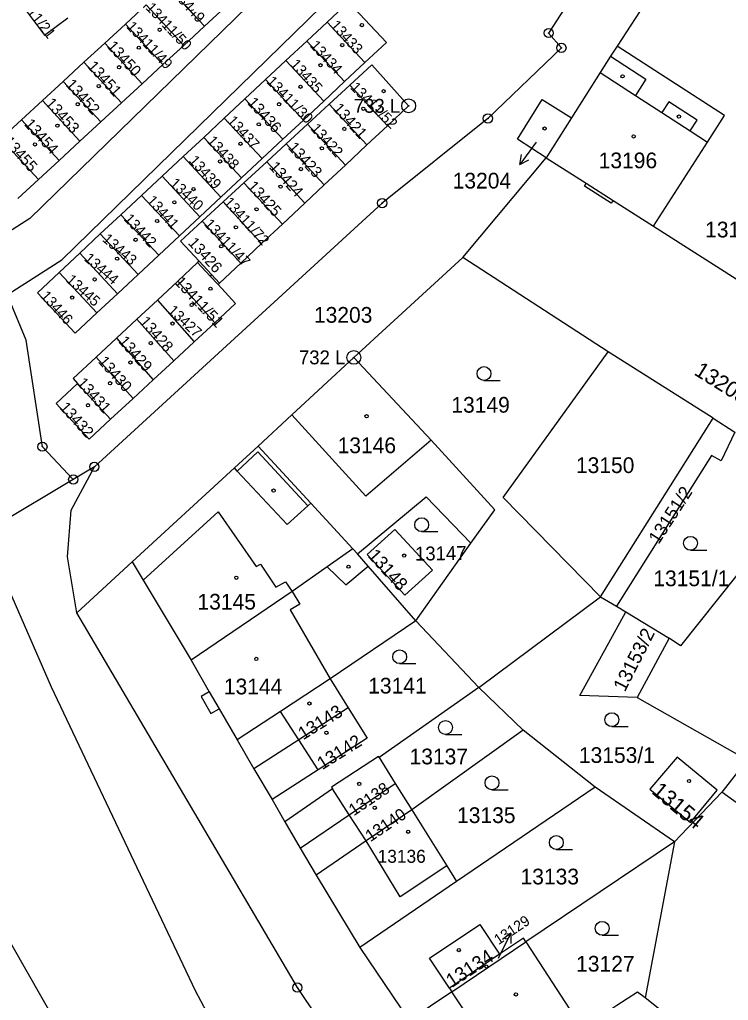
# Model space of a CAD drawing. Extents: x -821458 to -820266, y -1071458 to -1069826.
# Drawn here: x -820643.1 to -820566.5, y -1071211.7 to -1071105.6 of the extents above; entities that cross this region are included whole.
import ezdxf

# ---------------------------------------------------------------- set-up
doc = ezdxf.new("R2010")
doc.units = 0
for name, color, linetype in [('Vrstva 1', 7, 'Continuous'), ('Vrstva 13', 7, 'Continuous'), ('Vrstva 2', 7, 'Continuous'), ('Vrstva 3', 7, 'Continuous'), ('Vrstva 4', 7, 'Continuous'), ('Vrstva 5', 7, 'Continuous'), ('Vrstva 6', 7, 'Continuous'), ('Vrstva 7', 7, 'Continuous'), ('Vrstva 8', 7, 'Continuous')]:
    doc.layers.add(name, color=color, linetype=linetype)

msp = doc.modelspace()

# ---------------------------------------------------------------- linework, layer by layer
at = {"layer": 'Vrstva 1'}
for p, q in [((-820571.9, -1071098.21), (-820578.53, -1071108.44)), ((-820623.14, -1071106.28), (-820627.21, -1071101.9)), ((-820629.45, -1071103.96), (-820631.7, -1071106.04)), ((-820625.38, -1071108.35), (-820629.45, -1071103.96)), ((-820623.14, -1071106.28), (-820620.9, -1071104.22)), ((-820609.89, -1071105.82), (-820612.09, -1071107.88)), ((-820609.89, -1071105.82), (-820605.79, -1071110.2)), ((-820631.7, -1071106.04), (-820633.93, -1071108.1)), ((-820631.7, -1071106.04), (-820627.63, -1071110.43)), ((-820625.38, -1071108.35), (-820623.14, -1071106.28)), ((-820612.09, -1071107.88), (-820614.34, -1071109.99)), ((-820612.09, -1071107.88), (-820608, -1071112.27)), ((-820633.93, -1071108.1), (-820636.17, -1071110.17)), ((-820633.93, -1071108.1), (-820629.87, -1071112.49)), ((-820627.63, -1071110.43), (-820625.38, -1071108.35)), ((-820614.34, -1071109.99), (-820616.55, -1071112.05)), ((-820610.25, -1071114.37), (-820614.34, -1071109.99)), ((-820636.17, -1071110.17), (-820638.42, -1071112.24)), ((-820636.17, -1071110.17), (-820632.11, -1071114.55)), ((-820629.87, -1071112.49), (-820627.63, -1071110.43)), ((-820608, -1071112.27), (-820605.79, -1071110.2)), ((-820616.55, -1071112.05), (-820618.78, -1071114.13)), ((-820616.55, -1071112.05), (-820612.45, -1071116.43)), ((-820638.42, -1071112.24), (-820640.67, -1071114.32)), ((-820638.42, -1071112.24), (-820634.35, -1071116.62)), ((-820632.11, -1071114.55), (-820629.87, -1071112.49)), ((-820610.25, -1071114.37), (-820608, -1071112.27)), ((-820607.43, -1071112.65), (-820609.66, -1071114.71)), ((-820607.43, -1071112.65), (-820603.37, -1071117.05)), ((-820618.78, -1071114.13), (-820621, -1071116.22)), ((-820618.78, -1071114.13), (-820614.68, -1071118.51)), ((-820640.67, -1071114.32), (-820642.94, -1071116.4)), ((-820640.67, -1071114.32), (-820636.61, -1071118.7)), ((-820634.35, -1071116.62), (-820632.11, -1071114.55)), ((-820612.45, -1071116.43), (-820610.25, -1071114.37)), ((-820609.66, -1071114.71), (-820611.99, -1071116.86)), ((-820609.66, -1071114.71), (-820605.58, -1071119.12)), ((-820642.94, -1071116.4), (-820645.16, -1071118.45)), ((-820642.94, -1071116.4), (-820638.87, -1071120.79)), ((-820621, -1071116.22), (-820623.23, -1071118.3)), ((-820621, -1071116.22), (-820616.91, -1071120.6)), ((-820614.68, -1071118.51), (-820612.45, -1071116.43)), ((-820583.46, -1071116.19), (-820586.18, -1071120.5)), ((-820636.61, -1071118.7), (-820634.35, -1071116.62)), ((-820611.99, -1071116.86), (-820614.3, -1071118.99)), ((-820611.99, -1071116.86), (-820607.9, -1071121.29)), ((-820605.58, -1071119.12), (-820603.37, -1071117.05)), ((-820645.16, -1071118.45), (-820641.09, -1071122.84)), ((-820623.23, -1071118.3), (-820625.46, -1071120.38)), ((-820623.23, -1071118.3), (-820619.14, -1071122.68)), ((-820616.91, -1071120.6), (-820614.68, -1071118.51)), ((-820638.87, -1071120.79), (-820636.61, -1071118.7)), ((-820614.3, -1071118.99), (-820616.41, -1071120.93)), ((-820614.3, -1071118.99), (-820610.19, -1071123.45)), ((-820607.9, -1071121.29), (-820605.58, -1071119.12)), ((-820625.46, -1071120.38), (-820627.72, -1071122.5)), ((-820625.46, -1071120.38), (-820621.36, -1071124.76)), ((-820619.14, -1071122.68), (-820616.91, -1071120.6)), ((-820595.21, -1071131.28), (-820586.18, -1071120.5)), ((-820641.09, -1071122.84), (-820638.87, -1071120.79)), ((-820616.41, -1071120.93), (-820618.87, -1071123.2)), ((-820616.41, -1071120.93), (-820612.28, -1071125.4)), ((-820610.19, -1071123.45), (-820607.9, -1071121.29)), ((-820627.72, -1071122.5), (-820629.95, -1071124.58)), ((-820627.72, -1071122.5), (-820623.63, -1071126.88)), ((-820621.36, -1071124.76), (-820619.14, -1071122.68)), ((-820643.33, -1071124.91), (-820641.09, -1071122.84)), ((-820618.87, -1071123.2), (-820621.12, -1071125.28)), ((-820618.87, -1071123.2), (-820614.72, -1071127.69)), ((-820612.28, -1071125.4), (-820610.19, -1071123.45)), ((-820629.95, -1071124.58), (-820632.18, -1071126.67)), ((-820629.95, -1071124.58), (-820625.86, -1071128.96)), ((-820623.63, -1071126.88), (-820621.36, -1071124.76)), ((-820621.12, -1071125.28), (-820623.38, -1071127.37)), ((-820616.96, -1071129.79), (-820621.12, -1071125.28)), ((-820614.72, -1071127.69), (-820612.28, -1071125.4)), ((-820632.18, -1071126.67), (-820634.41, -1071128.75)), ((-820632.18, -1071126.67), (-820628.08, -1071131.05)), ((-820625.86, -1071128.96), (-820623.63, -1071126.88)), ((-820623.38, -1071127.37), (-820619.2, -1071131.89)), ((-820616.96, -1071129.79), (-820614.72, -1071127.69)), ((-820574.58, -1071127.9), (-820563.75, -1071134.82)), ((-820634.41, -1071128.75), (-820636.63, -1071130.83)), ((-820634.41, -1071128.75), (-820630.31, -1071133.13)), ((-820628.08, -1071131.05), (-820625.86, -1071128.96)), ((-820619.2, -1071131.89), (-820616.96, -1071129.79)), ((-820636.63, -1071130.83), (-820638.86, -1071132.91)), ((-820636.63, -1071130.83), (-820632.54, -1071135.21)), ((-820630.31, -1071133.13), (-820628.08, -1071131.05)), ((-820595.21, -1071131.28), (-820607, -1071142.1)), ((-820579.48, -1071141.51), (-820595.21, -1071131.28)), ((-820638.86, -1071132.91), (-820634.77, -1071137.29)), ((-820632.54, -1071135.21), (-820630.31, -1071133.13)), ((-820626.04, -1071133.86), (-820628.24, -1071135.91)), ((-820622.04, -1071138.36), (-820626.04, -1071133.86)), ((-820634.77, -1071137.29), (-820632.54, -1071135.21)), ((-820628.24, -1071135.91), (-820630.45, -1071137.97)), ((-820628.24, -1071135.91), (-820624.25, -1071140.4)), ((-820630.45, -1071137.97), (-820632.66, -1071140.03)), ((-820630.45, -1071137.97), (-820626.46, -1071142.46)), ((-820624.25, -1071140.4), (-820622.04, -1071138.36)), ((-820632.66, -1071140.03), (-820634.84, -1071142.06)), ((-820632.66, -1071140.03), (-820628.68, -1071144.51)), ((-820626.46, -1071142.46), (-820624.25, -1071140.4)), ((-820568.13, -1071148.68), (-820579.48, -1071141.51)), ((-820634.84, -1071142.06), (-820630.87, -1071146.53)), ((-820628.68, -1071144.51), (-820626.46, -1071142.46)), ((-820636.86, -1071144.91), (-820633.29, -1071148.77)), ((-820630.87, -1071146.53), (-820628.68, -1071144.51)), ((-820633.29, -1071148.77), (-820630.87, -1071146.53)), ((-820580.31, -1071167.99), (-820568.13, -1071148.68)), ((-820568.13, -1071148.68), (-820565.8, -1071150.18)), ((-820635.05, -1071153.94), (-820637.33, -1071155.3)), ((-820637.33, -1071155.3), (-820662, -1071170.07)), ((-820606.61, -1071163.36), (-820607.09, -1071162.81)), ((-820600.3, -1071170.6), (-820594.33, -1071162.21)), ((-820636.96, -1071169.72), (-820630.96, -1071164.21)), ((-820593.49, -1071177.8), (-820580.31, -1071167.99)), ((-820580.31, -1071167.99), (-820578.6, -1071169.02)), ((-820578.6, -1071169.02), (-820577.58, -1071169.64)), ((-820577.58, -1071169.64), (-820572.9, -1071172.46)), ((-820600.3, -1071170.6), (-820609.55, -1071176.86)), ((-820593.49, -1071177.8), (-820600.3, -1071170.6)), ((-820572.9, -1071172.46), (-820576.35, -1071178.9)), ((-820609.55, -1071176.86), (-820607.6, -1071180)), ((-820593.49, -1071177.8), (-820604.26, -1071185.37)), ((-820588.7, -1071182.42), (-820593.49, -1071177.8)), ((-820576.35, -1071178.9), (-820564.47, -1071185.62)), ((-820588.7, -1071182.42), (-820600.74, -1071191.03)), ((-820580.89, -1071188.58), (-820588.7, -1071182.42)), ((-820619.61, -1071183.48), (-820617.79, -1071186.59)), ((-820604.26, -1071185.37), (-820602.51, -1071188.18)), ((-820564.47, -1071185.62), (-820567.22, -1071189.13)), ((-820617.79, -1071186.59), (-820615.84, -1071189.94)), ((-820602.51, -1071188.18), (-820600.74, -1071191.03)), ((-820580.89, -1071188.58), (-820595.88, -1071198.8)), ((-820572.31, -1071194.51), (-820580.89, -1071188.58)), ((-820567.22, -1071189.13), (-820572.31, -1071194.51)), ((-820615.84, -1071189.94), (-820614.45, -1071192.34)), ((-820614.45, -1071192.34), (-820612.78, -1071195.19)), ((-820572.31, -1071194.51), (-820588.39, -1071205.33)), ((-820572.31, -1071194.51), (-820575.48, -1071211.38)), ((-820612.78, -1071195.19), (-820611.07, -1071198.11)), ((-820611.07, -1071198.11), (-820606.35, -1071205.94)), ((-820595.88, -1071198.8), (-820606.35, -1071205.94)), ((-820596.4, -1071210.72), (-820588.39, -1071205.33)), ((-820588.39, -1071205.33), (-820582.26, -1071214.75)), ((-820606.35, -1071205.94), (-820601.01, -1071213.82)), ((-820591.23, -1071206.67), (-820596.65, -1071210.34)), ((-820596.4, -1071210.72), (-820601.01, -1071213.82)), ((-820596.65, -1071210.34), (-820596.4, -1071210.72)), ((-820590.11, -1071220.12), (-820596.4, -1071210.72)), ((-820565.25, -1071219.52), (-820575.48, -1071211.38))]:
    msp.add_line(p, q, dxfattribs=at)
for points in [[(-820637.33, -1071155.3), (-820640.67, -1071151.76), (-820642.44, -1071140.23), (-820649.73, -1071122.67), (-820650.36, -1071093.83)], [(-820571.9, -1071098.21), (-820578.09, -1071094.87), (-820585.93, -1071107.01), (-820584.55, -1071108.62), (-820592.5, -1071116.26), (-820603.93, -1071125.41), (-820635.05, -1071153.94)], [(-820641.91, -1071100.01), (-820644.43, -1071101.87), (-820640.43, -1071107.25), (-820637.92, -1071105.38)], [(-820605.79, -1071110.2), (-820603.47, -1071108.04), (-820607.58, -1071103.67), (-820609.89, -1071105.82)], [(-820578.53, -1071108.44), (-820579.23, -1071109.52), (-820580.37, -1071111.29), (-820583.46, -1071116.19)], [(-820574.58, -1071127.9), (-820568.75, -1071118.8), (-820566.92, -1071115.95), (-820578.53, -1071108.44)], [(-820603.37, -1071117.05), (-820601.07, -1071114.89), (-820605.04, -1071110.45), (-820607.43, -1071112.65)], [(-820586.18, -1071120.5), (-820589.29, -1071118.51), (-820586.63, -1071114.19), (-820583.46, -1071116.19)], [(-820586.18, -1071120.5), (-820581.86, -1071123.26), (-820578.96, -1071125.11), (-820574.58, -1071127.9)], [(-820623.38, -1071127.37), (-820625.74, -1071129.54), (-820623.73, -1071131.7)], [(-820623.73, -1071131.7), (-820623.89, -1071131.85), (-820626.04, -1071133.86)], [(-820623.73, -1071131.7), (-820622.37, -1071133.15), (-820622.53, -1071133.31), (-820621.68, -1071134.22)], [(-820621.68, -1071134.22), (-820621.51, -1071134.06), (-820619.2, -1071131.89)], [(-820638.86, -1071132.91), (-820641.2, -1071135.1), (-820637.11, -1071139.48), (-820634.77, -1071137.29)], [(-820622.04, -1071138.36), (-820619.78, -1071136.28), (-820621.68, -1071134.22)], [(-820580.31, -1071167.99), (-820590.84, -1071157.27), (-820579.48, -1071141.51)], [(-820634.84, -1071142.06), (-820637.34, -1071144.39), (-820636.86, -1071144.91)], [(-820607, -1071142.1), (-820613.71, -1071148.32), (-820617.33, -1071151.69)], [(-820594.33, -1071162.21), (-820591.74, -1071158.58), (-820598.65, -1071151.04), (-820607, -1071142.1)], [(-820636.86, -1071144.91), (-820639.19, -1071147.07), (-820635.62, -1071150.93), (-820633.29, -1071148.77)], [(-820565.8, -1071150.18), (-820567.29, -1071153.29), (-820568.31, -1071152.7), (-820578.6, -1071169.02)], [(-820617.33, -1071151.69), (-820619.91, -1071154.06), (-820630.96, -1071164.21)], [(-820607.09, -1071162.81), (-820611.64, -1071157.87), (-820617.33, -1071151.69)], [(-820636.96, -1071169.72), (-820637.97, -1071163.66), (-820637.57, -1071158.64), (-820635.05, -1071153.94)], [(-820557.49, -1071155.53), (-820571.69, -1071173.31), (-820572.9, -1071172.46)], [(-820606.61, -1071163.36), (-820599.18, -1071157.18), (-820594.33, -1071162.21)], [(-820602.56, -1071160.73), (-820598.48, -1071165.13), (-820601.47, -1071167.82), (-820605.56, -1071163.42), (-820602.56, -1071160.73)], [(-820607.09, -1071162.81), (-820609.89, -1071164.76), (-820613.66, -1071167.42), (-820624.6, -1071174.87)], [(-820600.3, -1071170.6), (-820605.45, -1071164.7), (-820606.61, -1071163.36)], [(-820630.96, -1071164.21), (-820629.77, -1071166.21), (-820624.6, -1071174.87)], [(-820564.58, -1071281.57), (-820567.96, -1071277.63), (-820613.1, -1071210.27), (-820636.96, -1071169.72)], [(-820576.35, -1071178.9), (-820582.57, -1071178.68), (-820577.85, -1071170.1), (-820577.58, -1071169.64)], [(-820624.6, -1071174.87), (-820622.62, -1071178.29), (-820621.57, -1071180.1), (-820619.61, -1071183.48)], [(-820609.55, -1071176.86), (-820614.93, -1071180.4), (-820619.61, -1071183.48)], [(-820607.6, -1071180), (-820612.95, -1071183.46), (-820617.79, -1071186.59)], [(-820607.6, -1071180), (-820605.56, -1071183.29), (-820610.85, -1071186.71), (-820615.84, -1071189.94)], [(-820604.26, -1071185.37), (-820604.33, -1071185.26), (-820609.41, -1071188.59), (-820609.3, -1071188.77), (-820614.45, -1071192.34)], [(-820574.98, -1071188.8), (-820570.6, -1071192.42), (-820567.7, -1071188.92), (-820572.02, -1071185.34), (-820574.98, -1071188.8)], [(-820612.78, -1071195.19), (-820607.49, -1071191.58), (-820602.51, -1071188.18)], [(-820556.62, -1071191.69), (-820558.93, -1071195.12), (-820567.22, -1071189.13)], [(-820600.74, -1071191.03), (-820605.67, -1071194.4), (-820611.07, -1071198.11)], [(-820600.74, -1071191.03), (-820596.94, -1071197.11), (-820595.88, -1071198.8)], [(-820637.88, -1071216.32), (-820639.21, -1071214.01), (-820645.44, -1071203.12)], [(-820596.65, -1071210.34), (-820598.82, -1071207.1), (-820593.37, -1071203.46), (-820591.23, -1071206.67)], [(-820588.39, -1071205.33), (-820588.65, -1071204.92), (-820591.23, -1071206.67)], [(-820575.48, -1071211.38), (-820576.31, -1071210.76), (-820578.57, -1071212.22), (-820579.84, -1071213.09), (-820582.26, -1071214.75)]]:
    msp.add_lwpolyline(points, dxfattribs=at)
at = {"layer": 'Vrstva 13'}
msp.add_lwpolyline([(-820675.1, -1071148.28), (-820672.81, -1071153.44), (-820638.57, -1071131.55), (-820610.44, -1071104.1), (-820600.08, -1071094.97), (-820582.77, -1071081.03), (-820585.78, -1071076.26), (-820603.68, -1071090.69), (-820614.26, -1071100), (-820642.01, -1071127.07)], close=True, dxfattribs=at)
at = {"layer": 'Vrstva 3'}
for p, q in [((-820592.92, -1071144.6), (-820591.17, -1071144.6)), ((-820599.66, -1071160.95), (-820597.91, -1071160.95)), ((-820570.59, -1071162.96), (-820568.84, -1071162.96)), ((-820602.04, -1071175.23), (-820600.29, -1071175.23)), ((-820579.09, -1071182.04), (-820577.34, -1071182.04)), ((-820597.08, -1071182.89), (-820595.33, -1071182.89)), ((-820592.06, -1071188.87), (-820590.31, -1071188.87)), ((-820585.1, -1071195.32), (-820583.35, -1071195.32)), ((-820580.14, -1071204.61), (-820578.39, -1071204.61))]:
    msp.add_line(p, q, dxfattribs=at)
for centre in [(-820592.92, -1071143.85), (-820599.66, -1071160.2), (-820570.59, -1071162.21), (-820602.04, -1071174.48), (-820579.09, -1071181.29), (-820597.08, -1071182.14), (-820592.06, -1071188.12), (-820585.1, -1071194.57), (-820580.14, -1071203.86)]:
    msp.add_circle(centre, 0.75, dxfattribs=at)
at = {"layer": 'Vrstva 4'}
for p, q in [((-820579.23, -1071109.52), (-820575.41, -1071111.99)), ((-820580.37, -1071111.29), (-820576.55, -1071113.76)), ((-820575.41, -1071111.99), (-820576.55, -1071113.76)), ((-820576.55, -1071113.76), (-820573.7, -1071115.6)), ((-820572.95, -1071114.45), (-820573.7, -1071115.6)), ((-820569.87, -1071116.44), (-820572.95, -1071114.45)), ((-820573.7, -1071115.6), (-820570.61, -1071117.6)), ((-820570.61, -1071117.6), (-820569.87, -1071116.44)), ((-820570.61, -1071117.6), (-820568.75, -1071118.8)), ((-820582.05, -1071123.56), (-820581.86, -1071123.26)), ((-820579.16, -1071125.41), (-820582.05, -1071123.56)), ((-820578.96, -1071125.11), (-820579.16, -1071125.41)), ((-820623.89, -1071131.85), (-820622.53, -1071133.31)), ((-820622.37, -1071133.15), (-820621.51, -1071134.06)), ((-820605.68, -1071157.1), (-820613.71, -1071148.32)), ((-820598.65, -1071151.04), (-820605.68, -1071157.1)), ((-820619.6, -1071154.39), (-820617.36, -1071152.32)), ((-820617.36, -1071152.32), (-820611.98, -1071158.17)), ((-820619.6, -1071154.39), (-820619.91, -1071154.06)), ((-820614.19, -1071160.17), (-820619.6, -1071154.39)), ((-820629.77, -1071166.21), (-820621.65, -1071158.79)), ((-820621.65, -1071158.79), (-820617.56, -1071164.73)), ((-820611.98, -1071158.17), (-820614.19, -1071160.17)), ((-820611.64, -1071157.87), (-820611.98, -1071158.17)), ((-820617.56, -1071164.73), (-820617.1, -1071164.45)), ((-820617.1, -1071164.45), (-820615.44, -1071166.94)), ((-820609.89, -1071164.76), (-820607.85, -1071166.71)), ((-820607.85, -1071166.71), (-820605.45, -1071164.7)), ((-820615.44, -1071166.94), (-820614.38, -1071166.38)), ((-820614.38, -1071166.38), (-820613.66, -1071167.42)), ((-820613.66, -1071167.42), (-820612.84, -1071168.81)), ((-820612.84, -1071168.81), (-820613.88, -1071169.41)), ((-820613.88, -1071169.41), (-820609.55, -1071176.86)), ((-820622.62, -1071178.29), (-820623.5, -1071178.79)), ((-820623.5, -1071178.79), (-820622.44, -1071180.61)), ((-820622.44, -1071180.61), (-820621.57, -1071180.1)), ((-820612.95, -1071183.46), (-820614.93, -1071180.4)), ((-820610.85, -1071186.71), (-820612.95, -1071183.46)), ((-820607.49, -1071191.58), (-820609.3, -1071188.77)), ((-820605.67, -1071194.4), (-820607.49, -1071191.58)), ((-820601.99, -1071200.45), (-820605.67, -1071194.4)), ((-820596.94, -1071197.11), (-820601.99, -1071200.45))]:
    msp.add_line(p, q, dxfattribs=at)
at = {"layer": 'Vrstva 5'}
for centre in [(-820627.99, -1071106.66), (-820606.12, -1071106.15), (-820630.24, -1071108.6), (-820608.25, -1071108.32), (-820632.37, -1071110.71), (-820610.6, -1071110.5), (-820577.94, -1071111.7), (-820634.57, -1071112.75), (-820612.76, -1071112.82), (-820603.77, -1071113.3), (-820636.84, -1071114.71), (-820615.07, -1071114.71), (-820605.97, -1071115.2), (-820571.85, -1071116.05), (-820639.04, -1071117.03), (-820617.27, -1071116.89), (-820608.02, -1071117.38), (-820586.37, -1071117.34), (-820576.74, -1071118.2), (-820641.47, -1071119.06), (-820619.25, -1071118.99), (-820610.45, -1071119.48), (-820621.45, -1071120.9), (-820612.72, -1071121.73), (-820624.33, -1071123.89), (-820614.92, -1071123.63), (-820626.4, -1071125.33), (-820617.51, -1071126.08), (-820628.27, -1071127.35), (-820619.74, -1071128.03), (-820630.59, -1071129.37), (-820621.33, -1071130.09), (-820632.59, -1071131.42), (-820635.02, -1071133.67), (-820637.45, -1071135.63), (-820622.49, -1071134.67), (-820624.53, -1071136.42), (-820626.6, -1071138.44), (-820628.95, -1071140.55), (-820631.15, -1071142.65), (-820633.35, -1071144.9), (-820635.74, -1071147.28), (-820605.62, -1071148.46), (-820615.67, -1071156.51), (-820601.55, -1071163.54), (-820607.57, -1071164.74), (-820619.7, -1071165.94), (-820617.54, -1071174.72), (-820611.8, -1071179.54), (-820609.96, -1071182.71), (-820606.41, -1071188.24), (-820570.75, -1071187.92), (-820604.73, -1071190.82), (-820601.12, -1071193.41), (-820595.64, -1071206.21), (-820592.67, -1071207.99), (-820589.47, -1071211.01)]:
    msp.add_circle(centre, 0.175, dxfattribs=at)
at = {"layer": 'Vrstva 6'}
for p, q in [((-820639.69, -1071177.76), (-820652.58, -1071148.22)), ((-820624.12, -1071210.63), (-820639.69, -1071177.76)), ((-820611.74, -1071233.47), (-820624.12, -1071210.63))]:
    msp.add_line(p, q, dxfattribs=at)
at = {"layer": 'Vrstva 7'}
for p, q in [((-820587.29, -1071118.82), (-820589.05, -1071121.25)), ((-820589.05, -1071121.25), (-820588.87, -1071120.14)), ((-820589.05, -1071121.25), (-820588.06, -1071120.73)), ((-820591.35, -1071207.09), (-820590.03, -1071204.39)), ((-820590.03, -1071204.39), (-820590.92, -1071205.07)), ((-820590.03, -1071204.39), (-820590.02, -1071205.51))]:
    msp.add_line(p, q, dxfattribs=at)
at = {"layer": 'Vrstva 8'}
for centre, radius in [((-820585.93, -1071107.01), 0.5), ((-820585.93, -1071107.01), 0.0303), ((-820584.55, -1071108.62), 0.5), ((-820584.55, -1071108.62), 0.0303), ((-820601.07, -1071114.89), 0.75), ((-820601.07, -1071114.89), 0.03), ((-820592.5, -1071116.26), 0.5), ((-820592.5, -1071116.26), 0.0303), ((-820603.93, -1071125.41), 0.5), ((-820603.93, -1071125.41), 0.0303), ((-820607, -1071142.1), 0.75), ((-820607, -1071142.1), 0.03), ((-820640.67, -1071151.76), 0.5), ((-820640.67, -1071151.76), 0.0303), ((-820635.05, -1071153.94), 0.5), ((-820635.05, -1071153.94), 0.0303), ((-820637.33, -1071155.3), 0.5), ((-820637.33, -1071155.3), 0.0303), ((-820613.1, -1071210.27), 0.5), ((-820613.1, -1071210.27), 0.0303)]:
    msp.add_circle(centre, radius, dxfattribs=at)

# ---------------------------------------------------------------- texts
at = {"layer": 'Vrstva 2'}
for s, height, rotation, p in [('13411/21', 1.139, 308, (-820643.96, -1071102.73)), ('13449', 1.139, 312, (-820626.66, -1071102.85)), ('13411/50', 1.139, 313, (-820629.57, -1071104.34)), ('13433', 1.139, 312, (-820609.59, -1071106.24)), ('13411/49', 1.139, 313, (-820631.65, -1071106.38)), ('13450', 1.2, 312, (-820633.75, -1071108.5)), ('13434', 1.139, 312, (-820611.8, -1071108.42)), ('13435', 1.139, 312, (-820613.94, -1071110.45)), ('13451', 1.2, 312, (-820635.87, -1071110.67)), ('13452', 1.2, 312, (-820638.22, -1071112.64)), ('13411/30', 1.139, 314, (-820616.51, -1071112.33)), ('13411/52', 1.139, 315, (-820607.45, -1071112.98)), ('13453', 1.2, 312, (-820640.42, -1071114.67)), ('13436', 1.2, 312, (-820618.58, -1071114.6)), ('13421', 1.2, 312, (-820609.32, -1071115.24)), ('13454', 1.2, 312, (-820642.7, -1071116.92)), ('13437', 1.139, 312, (-820620.76, -1071116.56)), ('13422', 1.139, 312, (-820611.73, -1071117.4)), ('13455', 1.2, 312, (-820644.97, -1071118.82)), ('13438', 1.139, 312, (-820622.95, -1071118.74)), ('13423', 1.2, 312, (-820614.18, -1071119.45)), ('13439', 1.139, 312, (-820624.89, -1071120.86)), ('13424', 1.2, 312, (-820616.22, -1071121.55)), ('13440', 1.139, 316, (-820626.97, -1071123.38)), ('13425', 1.2, 312, (-820618.58, -1071123.66)), ('13441', 1.139, 312, (-820629.46, -1071125.19)), ('13411/72', 1.139, 312, (-820621.13, -1071125.37)), ('13442', 1.139, 313, (-820631.93, -1071127.19)), ('13411/47', 1.139, 313, (-820623.24, -1071127.75)), ('13443', 1.139, 319, (-820634.27, -1071129.44)), ('13426', 1.2, 312, (-820624.99, -1071129.76)), ('13444', 1.139, 319, (-820636.24, -1071131.54)), ('13445', 1.139, 318, (-820638.19, -1071133.84)), ('13411/51', 1.218, 313, (-820626.46, -1071134.02)), ('13446', 1.139, 312, (-820640.94, -1071135.51)), ('13427', 1.139, 317, (-820627.19, -1071137.15)), ('13428', 1.2, 311, (-820630.24, -1071138.28)), ('13429', 1.2, 311, (-820632.51, -1071140.4)), ('13430', 1.2, 311, (-820634.71, -1071142.58)), ('13205', 1.7, 328, (-820570.31, -1071143.91)), ('13431', 1.2, 312, (-820637.01, -1071144.93)), ('13432', 1.2, 312, (-820638.88, -1071147.57)), ('13151/2', 1.416, 57, (-820574.04, -1071162.39)), ('13148', 1.4, 312, (-820605.56, -1071163.59)), ('13147', 1.5, 1, (-820600.37, -1071164.09)), ('13153/2', 1.502, 63, (-820577.69, -1071178.36)), ('13143', 1.4, 32, (-820612.47, -1071183.53)), ('13142', 1.4, 32, (-820610.41, -1071186.76)), ('13138', 1.3, 34, (-820607, -1071191.75)), ('13154', 1.7, 320, (-820574.89, -1071189.19)), ('13140', 1.3, 34, (-820605.2, -1071194.55)), ('13129', 1.139, 34, (-820591.35, -1071205.69)), ('13134', 1.5, 33, (-820596.41, -1071210.33))]:
    msp.add_text(s, height=height, rotation=rotation, dxfattribs=at).set_placement(p)
for s, height, p in [('13196', 1.7, (-820580.52, -1071121.64)), ('13204', 1.7, (-820596.31, -1071123.83)), ('13195/2', 1.7, (-820569.01, -1071129.12)), ('13203', 1.7, (-820611.31, -1071138.35)), ('13149', 1.7, (-820596.45, -1071148.08)), ('13146', 1.7, (-820608.75, -1071152.46)), ('13150', 1.7, (-820582.98, -1071154.61)), ('13151/1', 1.7, (-820574.61, -1071166.85)), ('13145', 1.7, (-820623.9, -1071169.38)), ('13144', 1.7, (-820621.05, -1071178.55)), ('13141', 1.7, (-820605.44, -1071178.46)), ('13153/1', 1.7, (-820582.66, -1071185.97)), ('13137', 1.7, (-820600.97, -1071186.12)), ('13135', 1.7, (-820595.83, -1071192.47)), ('13136', 1.4, (-820604.42, -1071196.77)), ('13133', 1.7, (-820588.97, -1071199.11)), ('13127', 1.7, (-820582.96, -1071208.54))]:
    msp.add_text(s, height=height, dxfattribs=at).set_placement(p)
at = {"layer": 'Vrstva 8'}
for s, p in [('733 L', (-820607, -1071115.64)), ('732 L', (-820612.93, -1071142.85))]:
    msp.add_text(s, height=1.5, dxfattribs=at).set_placement(p)

doc.saveas('drawing.dxf')
